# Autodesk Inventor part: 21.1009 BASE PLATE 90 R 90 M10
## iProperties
Created: 2009-01
Part Number: 21.1009 BASE PLATE 90 R 90 M10
Document SubType Name: Modeling
Designer: Administrator
Density: 1 g/cm^3
Author: Administrator
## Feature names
1. Base1
